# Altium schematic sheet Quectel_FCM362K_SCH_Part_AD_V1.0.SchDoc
size A2; Organization: Altium Limited; Address1: L3, 12a Rodborough Rd; Address2: Frenchs Forest; Address3: NSW; Address4: Australia 2086
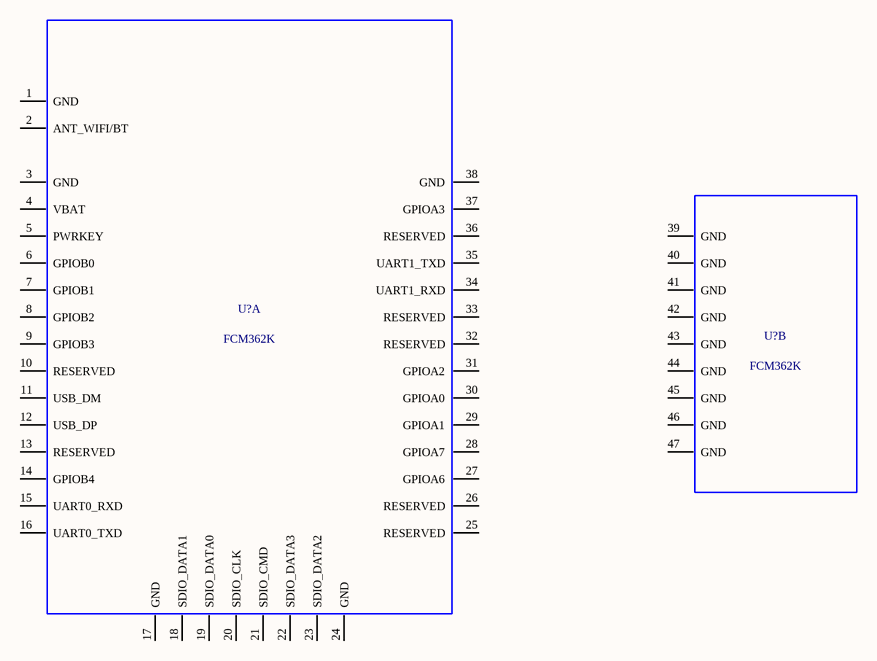
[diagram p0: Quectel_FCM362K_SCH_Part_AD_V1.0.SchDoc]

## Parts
(Parts that share a designator on the sheet are numbered #1, #2 ... from top to bottom, then left to right.)
U?#1  FCM362K  [FCM362K]  (part A of 2)
U?#2  FCM362K  [FCM362K]  (part B of 2)

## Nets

Not connected (* = marked no-connect by the designer): U?#1 1(GND) 2(ANT_WIFI/BT) 3(GND) 4(VBAT) 5(PWRKEY) 6(GPIOB0) 7(GPIOB1) 8(GPIOB2) 9(GPIOB3) 10(RESERVED) 11(USB_DM) 12(USB_DP) 13(RESERVED) 14(GPIOB4) 15(UART0_RXD) 16(UART0_TXD) 17(GND) 18(SDIO_DATA1) 19(SDIO_DATA0) 20(SDIO_CLK) 21(SDIO_CMD) 22(SDIO_DATA3) 23(SDIO_DATA2) 24(GND) 25(RESERVED) 26(RESERVED) 27(GPIOA6) 28(GPIOA7) 29(GPIOA1) 30(GPIOA0) 31(GPIOA2) 32(RESERVED) 33(RESERVED) 34(UART1_RXD) 35(UART1_TXD) 36(RESERVED) 37(GPIOA3) 38(GND); U?#2 39(GND) 40(GND) 41(GND) 42(GND) 43(GND) 44(GND) 45(GND) 46(GND) 47(GND)

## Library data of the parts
U?#1 U?#2 = FCM362K: FCM362K Module 47PIN 25.5X18mm H3.15mm RO; Manufacturer: Quectel; Geometry.Height: 3.15mm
